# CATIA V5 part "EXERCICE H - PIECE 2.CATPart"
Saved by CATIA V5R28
Part number: Exercice H - B
Bounding box of the stored display mesh (mm): x -6 to 6, y -6 to 6, z 0 to 24
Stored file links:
  \\stisrv.epfl.ch\sti-sgm\sgm-ens\soubiell\Enseignement\ME-101-106 - Construction Mécanique I\1. Supports de cours\Z. Archives\2020\SW3\Modèles 3D exercice H\EXERCICE H - PIECE 2.CATPart
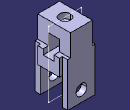
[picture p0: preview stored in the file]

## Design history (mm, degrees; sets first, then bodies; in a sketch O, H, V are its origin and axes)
Body1 (main body)
  Sketch1 on xy-plane, origin (0, 0, 0), H (1, 0, 0), V (0, 1, 0)
    line L1 (6, 4) -> (5, 4)
    line L2 (5, 4) -> (5, 6)
    line L3 (5, 6) -> (-5, 6)
    line L4 (-5, 6) -> (-5, 4)
    line L5 (-5, 4) -> (-6, 4)
    line L6 (-6, 4) -> (-6, -4)
    line L7 (-6, -4) -> (-5, -4)
    point P8 (-5, -4)
    line L8 (-5, -4) -> (-5, -6)
    line L9 (-5, -6) -> (5, -6)
    point P10 (5, -6)
    line L10 (5, -6) -> (5, -4)
    line L11 (5, -4) -> (6, -4)
    line L12 (6, -4) -> (6, 4)
    distance L12 L6 = 12
    distance L3 L9 = 12
    length L1 = 1
    length L2 = 2
    distance H L3 = 6
    distance V L12 = 6
    horizontal: L1 H, L3 H, L5 H, L7 H, L9 H, L11 H
    vertical: L2 V, L4 V, L6 V, L8 V, L10 V, L12 V
    coincidence: P8 L4, P10 L2, L7 L11, L5 L1
    equal size: L5 L7, L7 L1, L10 L2
  Pad1: profile Sketch1, direction (0, 0, 1), length 24
  Sketch2 on end face of Pad1, origin (0, 0, 24), H (1, 0, 0), V (0, 1, 0)
    line L1 (6, 6) -> (4, 6)
    line L2 (4, 6) -> (4, -6)
    line L3 (4, -6) -> (6, -6)
    line L4 (6, -6) -> (6, 6)
    line L5 (-4, 6) -> (-6, 6)
    line L6 (-6, 6) -> (-6, -6)
    line L7 (-6, -6) -> (-4, -6)
    line L8 (-4, -6) -> (-4, 6)
    reference projected line E1 (5, 6) -> (-5, 6) from edge [face of Pad1 from Sketch1.L3 | end face of Pad1]
    reference projected line E2 (5, 6) -> (-5, 6) from edge [face of Pad1 from Sketch1.L3 | end face of Pad1]
    reference projected line E3 (-5, -6) -> (5, -6) from edge [face of Pad1 from Sketch1.L9 | end face of Pad1]
    reference projected line E4 (-5, -6) -> (5, -6) from edge [face of Pad1 from Sketch1.L9 | end face of Pad1]
    reference projected line E5 (-6, 4) -> (-6, -4) from edge [face of Pad1 from Sketch1.L6 | end face of Pad1]
    reference projected line E6 (6, -4) -> (6, 4) from edge [face of Pad1 from Sketch1.L12 | end face of Pad1]
    length L1 = 2
    horizontal: L1 H, L3 H, L5 H, L7 H
    vertical: L2 V, L4 V, L6 V, L8 V
    coincidence: L5 E1, E2 L1, L3 E3, L7 E4, L6 E5, L4 E6
    equal size: L5 L1
  Pocket1: profile Sketch2, direction (0, 0, -1), length 8
  Sketch3 on face of Pad1 from Sketch1.L12, origin (6, -12, 0), H (0, 1, 0), V (0, 0, 1)
    line L1 (10, 20) -> (14, 20)
    line L2 (14, 20) -> (14, 14)
    line L3 (14, 14) -> (10, 14)
    line L4 (10, 14) -> (10, 20)
    reference projected line E1 (18, 24) -> (6, 24) from edge [end face of Pad1 | face of Pocket1 from Sketch2.L2]
    reference intersected line E2 through (12, 0) direction (0, 1) from zx-plane
    distance L1 E1 = 4
    length L4 = 6
    length L1 = 4
    distance E2 L4 = 2
    horizontal: L1 H, L3 H
    vertical: L2 V, L4 V
  Pocket2: profile Sketch3, direction (-1, 0, 0), through (limit type 3)
  Sketch4 on face of Pad1 from Sketch1.L12, origin (6, -12, 0), H (0, 1, 0), V (0, 0, 1)
    line L1 (16, 10) -> (8, 10)
    line L2 (8, 10) -> (8, 0)
    line L3 (8, 0) -> (16, 0)
    line L4 (16, 0) -> (16, 10)
    point P3 (8, 0)
    reference projected line E1 (16, 0) -> (16, 24) from edge [face of Pad1 from Sketch1.L1 | face of Pad1 from Sketch1.L12]
    reference projected line E2 (8, 0) -> (8, 24) from edge [face of Pad1 from Sketch1.L12 | face of Pad1 from Sketch1.L11]
    length L4 = 10
    horizontal: L1 H, L3 H
    vertical: L2 V, L4 V
    coincidence: P3 H, L4 E1, L2 E2
  Pocket3: profile Sketch4, direction (-1, 0, 0), through (limit type 3)
  Sketch5 on face of Pad1 from Sketch1.L3, origin (-12, 6, 0), H (-1, 0, 0), V (0, 0, 1)
    circle A1 centre (-12, 4) radius 2
    point P1 (-12, 4)
    reference intersected line E1 through (-12, 0) direction (0, -1) from yz-plane
    reference projected line E2 (-17, 0) -> (-7, 0) from edge [start face of Pad1 | face of Pad1 from Sketch1.L3]
    distance P1 E2 = 4
    radius A1 = 2
    coincidence: P1 E1
  Pocket4: profile Sketch5, direction (0, 1, 0), through (limit type 3)
  Sketch6 on end face of Pad1, origin (0, 0, 24), H (1, 0, 0), V (0, 1, 0)
    point P1 (0, 0)
    coincidence: P1 H
  Hole1: placed by Sketch6, at (0, 0, 24) direction (0, 0, -1), diameter 4, depth 2, V-bottom angle 120
  Sketch7 "PLAN DE COUPE B-B" on zx-plane, origin (0, 0, 0), H (-1, 0, 0), V (0, 0, 1)
    point P1 (6, 0)
    line L1 (6, 0) -> (-6, 0)
    line L2 (-6, 0) -> (-6, 24)
    line L3 (-6, 24) -> (6, 24)
    line L4 (6, 24) -> (6, 0)
    coincidence: P1 H
    horizontal: L1 H, L3 H
    vertical: L2 V, L4 V
  Pocket5 "COUPE B-B": profile Sketch7, direction (0, -1, 0), through (limit type 6)
Current feature: Hole1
